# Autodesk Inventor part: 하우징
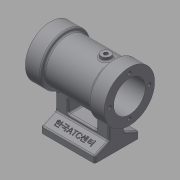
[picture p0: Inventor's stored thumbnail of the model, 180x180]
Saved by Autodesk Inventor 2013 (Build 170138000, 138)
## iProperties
Created: 2018-01
Part Number: 하우징
Material: 알루미늄 6061
Document SubType Name: Modeling
Designer: mduedu
Density: 2.71 g/cm^3
Mass: 74.6881 g
Surface Area: 127.588 cm^2
Volume: 27.5602 cm^3
Author: mduedu
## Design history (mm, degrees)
sketch "스케치1"
  geometry: L1 (-25, 0)-(25, 0); L2 (-25, 0)-(-25, 16); L3 (-25, 16)-(-15, 16); L4 (-15, 16)-(-15, 14); L5 (-15, 14)-(15, 14); L6 (15, 14)-(15, 16); L7 (15, 16)-(25, 16); L8 (25, 16)-(25, 0); 2 further points
  constraints: 16 end point, 3 parallel, 2 collinear, 2 perpendicular, 1 coincident, 1 horizontal, 1 midpoint, 1 vertical
  dimensions: "d0" = 50 distance of L1.start L1.end; "d2" = 10 distance of L2.end L3.end; "d3" = 10 distance of L6.end L7.end (= d2); "d4" = 32 diameter of L3 L1; "d5" = 28 diameter of L5 L1
revolve "회전1" sketch "스케치1" stored, may be unused: angle "d6" = 90 deg
hole "구멍1" diameter "d9" = 20; stored, may be unused: countersink angle "d13" = 90 deg, drill point angle "d15" = 118 deg; dims "d7" = 10, "d8" = 10, "d10" = 6, "d11" = 4, "d12" = 2, "d14" = 8
fillet "모깎기1" dims "d16" = 1
sketch "스케치2"
  geometry: L1 (0, 0)-(-34, 0); L2 (-34, 14)-(-34, -14); L3 (-34, 14)-(-30, 14); L4 (-30, 14)-(-26, 5); L5 (-26, 5)-(-13.077, 5); L6 (-26, -5)-(-13.077, -5); L7 (-30, -14)-(-26, -5); L8 (-34, -14)-(-30, -14); C1 r 10 at (0, 0) reference; A1 r 14 centre (0, 0) between (-13.077, 5) and (-13.077, -5); 2 further points
  constraints: 16 end point, 3 symmetric about line, 2 perpendicular, 2 point on circle, 1 centre point, 1 coincident, 1 horizontal, 1 midpoint, 1 parallel, 2 other
  dimensions: "d17" = 34 distance of L1.end L1.start; "d18" = 28 distance between parallel lines of L8 L3; "d19" = 10 distance between parallel lines of L6 L5; "d20" = 4 distance of L2.end L7.start; "d21" = 8 distance from line of L6.start L2
extrude "돌출1" join sketch "스케치2" stored distance "d22" = 34; taper "d23" = 0 deg
sketch "스케치3"
  geometry: L1 (-9, -16)-(9, -16); L2 (9, -16)-(9, -24); L3 (9, -24)-(-9, -24); L4 (-9, -24)-(-9, -16); L5 (-17, -15.199)-(-17, -26) reference; L6 (17, -26)-(17, -15.199) reference; L7 (-17, -34)-(17, -34) reference; 1 further point
  constraints: 8 end point, 2 parallel, 1 horizontal, 1 perpendicular
  dimensions: "d24" = 8 distance between parallel lines of L4 L5; "d25" = 8 distance between parallel lines of L2 L6; "d26" = 10 distance between parallel lines of L3 L7; "d27" = 8 distance of L1.end L2.end
extrude "돌출2" cut sketch "스케치3" stored distance "d28" = 34; taper "d29" = 0 deg
fillet "모깎기2" dims "d30" = 1
fillet "모깎기3" dims "d31" = 1
fillet "모깎기4" dims "d32" = 1
fillet "모깎기5" dims "d33" = 1
fillet "모깎기6" dims "d34" = 1
sketch "스케치4"
  geometry: 4 further points
  constraints: 4 other
hole "구멍2" sketch "스케치4" at (-12.5, 0), (0, -12.5), (12.5, 0), (0, 12.5) diameter "d35" = 2.459; stored, may be unused: countersink angle "d39" = 90 deg, drill point angle "d41" = 120 deg; dims "d36" = 5.5, "d37" = 4, "d38" = 2, "d40" = 7
sketch "스케치5"
  geometry: 4 further points
  constraints: 4 other
hole "구멍4" sketch "스케치5" at (-12.5, 0), (0, -12.5), (12.5, 0), (0, 12.5) diameter "d42" = 2.459; stored, may be unused: countersink angle "d46" = 90 deg, drill point angle "d48" = 120 deg; dims "d43" = 5.5, "d44" = 4, "d45" = 2, "d47" = 7
sketch "스케치6"
  geometry: 2 further points
  constraints: 2 other
hole "구멍5" sketch "스케치6" at (7, 14), (25, 14) diameter "d49" = 2.459; stored, may be unused: countersink angle "d53" = 90 deg, drill point angle "d55" = 120 deg; dims "d50" = 6.9, "d51" = 4, "d52" = 2, "d54" = 8.4
node "작업 평면1"
sketch "스케치7"
  geometry: L1 (-25, 16)-(-25, -16) reference; C1 r 3 at (-10, 0); 1 further point
  constraints: 1 centre point, 1 horizontal alignment
  dimensions: "d57" = 6 diameter of C1; "d60" = 15 distance from line of C1.centre L1
extrude "돌출3" join sketch "스케치7" stored distance "d61" = 10; taper "d62" = 0 deg
fillet "모깎기7" dims "d63" = 1
hole "구멍6" diameter "d66" = 2.459; stored, may be unused: countersink angle "d70" = 90 deg, drill point angle "d72" = 118 deg; dims "d64" = 10, "d65" = 10, "d67" = 6, "d68" = 4, "d69" = 2, "d71" = 8
sketch "스케치8"
  geometry: L1 (-1, 0)-(0, 0) reference; L2 (0, 0)-(0, 8.549) reference; L3 (0, 8.549)-(-1, 8.549) reference; L4 (-1, 8.549)-(-1, 0) reference; L5 (32, 0)-(33, 0) reference; L6 (33, 0)-(33, 8.549) reference; L7 (32, 8.549)-(33, 8.549) reference; L8 (32, 8.549)-(32, 0) reference; 3 further points
  constraints: 1 horizontal alignment, 1 midpoint, 1 vertical alignment, 1 other
feature "엠보싱1" sketch "스케치8" dims "d73" = 0.5, "d74" = 0
node "솔리드1"
node "투영된 루프1"
node "투영된 루프2"
node "절단 모서리 투영1"
other parameters: "d56" = 16
